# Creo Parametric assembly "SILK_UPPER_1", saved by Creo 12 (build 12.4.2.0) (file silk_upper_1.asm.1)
Units: Custom; MM, KILOGRAM, SECS

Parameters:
  PTC_WM_ITERATION = "0"
  PTC_WM_VERSION = "-.0"
  PTC_WM_LIFECYCLE_STATE = "In Work"
  PTC_WM_LIFECYCLE = "MO_CADDocument"
  PTC_WM_CREATED_BY = "Maximilian Roepper (Z0017RMS: MO)"
  PTC_WM_CREATED_ON = "18-Sep-26 11:36:42 AM"
  PTC_WM_MODIFIED_BY = "Maximilian Roepper (Z0017RMS: MO)"
  PTC_WM_MODIFIED_ON = "18-Sep-26 11:36:46 AM"
  PDMLINKNUMBER = "PDM000071455325"
  PTC_WM_NUMBER = "PDM000071455325"

Other parameters: WEIGHT, WEIGHT_FACTOR, WEIGHT_ADD, MC_ERRORS, SUPPLIER

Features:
  1. coordinate system
  2. imported feature
  3. component "CIRCLE001"
  4. component "CIRCLE002"
  5. component "CIRCLE003"
  6. component "CIRCLE004"
  7. component "BORDER001_1"
  8. component "BORDER002_1"
  9. component "SHAPESTRING101_1"
  10. component "SHAPESTRING104_1"

Other named items: DRW_VIEW_ORG, ROUGH-GROB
